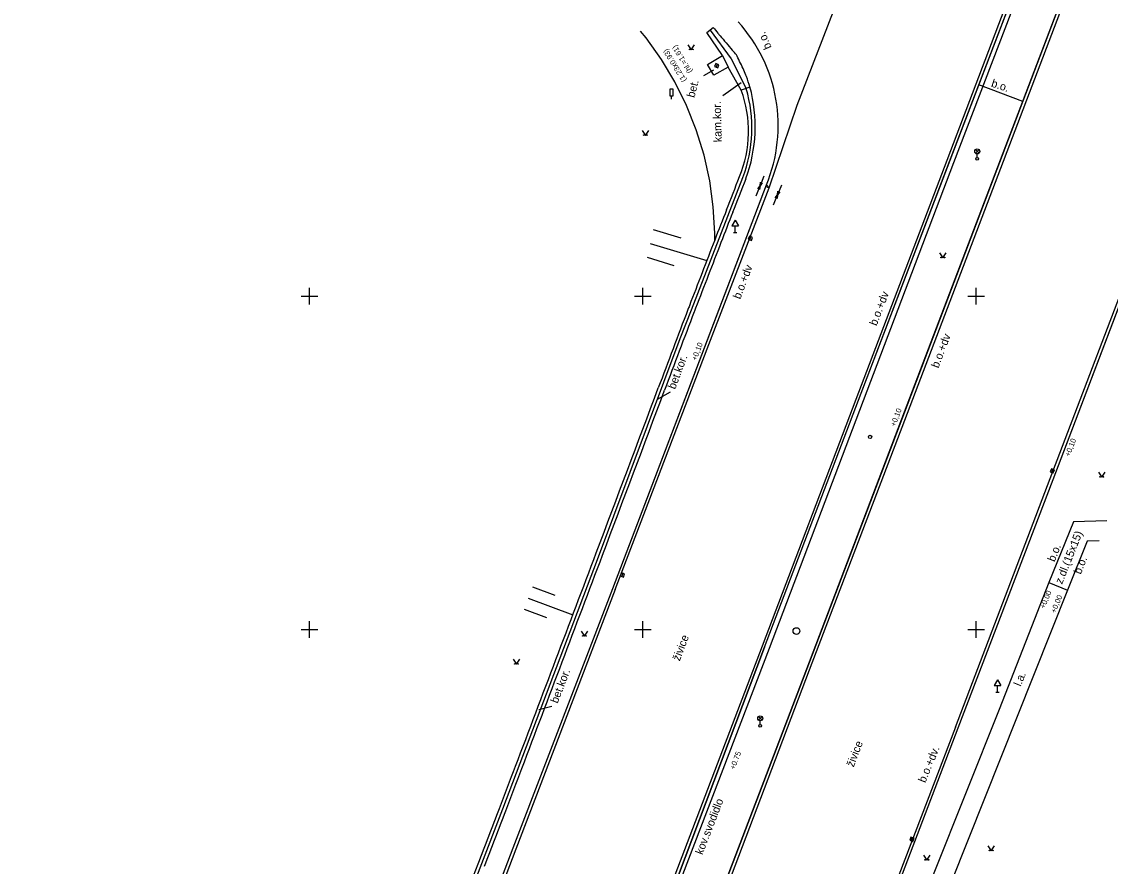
# Model space of a CAD drawing. Extents: x -599151 to -598424, y -1163476 to -1161924.
# Drawn here: x -598821.6 to -598740, y -1162867.7 to -1162804.4 of the extents above; entities that cross this region are included whole.
import ezdxf

# ---------------------------------------------------------------- set-up
doc = ezdxf.new("R2010")
doc.units = 0
for name, color, linetype in [('Vrstva 14', 7, 'Continuous'), ('Vrstva 15', 7, 'Continuous'), ('Vrstva 19', 7, 'Continuous'), ('Vrstva 21', 7, 'Continuous'), ('Vrstva 23', 7, 'Continuous'), ('Vrstva 25', 7, 'Continuous'), ('Vrstva 29', 7, 'Continuous'), ('Vrstva 41', 7, 'Continuous'), ('Vrstva 49', 7, 'Continuous'), ('Vrstva 50', 7, 'Continuous'), ('Vrstva 62', 7, 'Continuous'), ('Vrstva 63', 7, 'Continuous'), ('Vrstva 7', 7, 'Continuous')]:
    doc.layers.add(name, color=color, linetype=linetype)

msp = doc.modelspace()

# ---------------------------------------------------------------- linework, layer by layer
at = {"layer": 'Vrstva 14'}
for points in [[(-598771.62, -1162806.148), (-598771.37, -1162806.523), (-598771.12, -1162806.148)], [(-598775.059, -1162812.575), (-598774.809, -1162812.95), (-598774.559, -1162812.575)], [(-598752.759, -1162821.754), (-598752.509, -1162822.129), (-598752.259, -1162821.754)], [(-598740.845, -1162838.197), (-598740.595, -1162838.572), (-598740.345, -1162838.197)], [(-598779.637, -1162850.128), (-598779.387, -1162850.503), (-598779.137, -1162850.128)], [(-598784.733, -1162852.228), (-598784.483, -1162852.603), (-598784.233, -1162852.228)], [(-598749.14, -1162866.212), (-598748.89, -1162866.587), (-598748.64, -1162866.212)], [(-598753.956, -1162866.913), (-598753.706, -1162867.288), (-598753.456, -1162866.913)]]:
    msp.add_lwpolyline(points, dxfattribs=at)
for centre in [(-598771.495, -1162806.498), (-598771.245, -1162806.498), (-598774.934, -1162812.925), (-598774.684, -1162812.925), (-598752.634, -1162822.104), (-598752.384, -1162822.104), (-598740.72, -1162838.547), (-598740.47, -1162838.547), (-598779.512, -1162850.478), (-598779.262, -1162850.478), (-598784.608, -1162852.578), (-598784.358, -1162852.578), (-598749.015, -1162866.562), (-598748.765, -1162866.562), (-598753.831, -1162867.263), (-598753.581, -1162867.263)]:
    msp.add_circle(centre, 0.025, dxfattribs=at)
at = {"layer": 'Vrstva 15'}
msp.add_line((-598772.85, -1162810.23), (-598772.85, -1162809.98), dxfattribs=at)
msp.add_lwpolyline([(-598772.975, -1162809.98), (-598772.725, -1162809.98), (-598772.725, -1162809.48), (-598772.975, -1162809.48)], close=True, dxfattribs=at)
at = {"layer": 'Vrstva 19'}
for p, q in [((-598768.08, -1162819.307), (-598768.33, -1162819.74)), ((-598768.33, -1162819.74), (-598767.83, -1162819.74)), ((-598768.08, -1162819.307), (-598767.83, -1162819.74)), ((-598768.08, -1162820.24), (-598768.08, -1162819.74)), ((-598768.205, -1162820.24), (-598767.955, -1162820.24)), ((-598748.4, -1162853.767), (-598748.65, -1162854.2)), ((-598748.4, -1162853.767), (-598748.15, -1162854.2)), ((-598748.65, -1162854.2), (-598748.15, -1162854.2)), ((-598748.525, -1162854.7), (-598748.275, -1162854.7)), ((-598748.4, -1162854.7), (-598748.4, -1162854.2))]:
    msp.add_line(p, q, dxfattribs=at)
at = {"layer": 'Vrstva 21'}
msp.add_lwpolyline([(-598695.78, -1162664.24), (-598699.97, -1162674.3), (-598702.11, -1162679.97), (-598709.91, -1162700.89), (-598717.13, -1162720.74), (-598723.5, -1162738.84), (-598727.94, -1162752.59), (-598729.98, -1162757.92), (-598744.45, -1162796.07), (-598751.7, -1162815.01), (-598765.52, -1162851.41), (-598773.26, -1162871.58), (-598779.91, -1162889.88), (-598781.91, -1162894.82), (-598784.85, -1162901.68), (-598795.29, -1162929.3), (-598803.04, -1162949.86), (-598814.6, -1162980.19)], dxfattribs=at)
at = {"layer": 'Vrstva 23'}
msp.add_circle((-598757.97, -1162835.56), 0.125, dxfattribs=at)
at = {"layer": 'Vrstva 25'}
for p, q in [((-598769.504, -1162807.837), (-598769.416, -1162807.603)), ((-598766.984, -1162820.787), (-598766.896, -1162820.553)), ((-598744.345, -1162838.217), (-598744.255, -1162837.983)), ((-598776.574, -1162846.017), (-598776.486, -1162845.783)), ((-598754.875, -1162865.837), (-598754.785, -1162865.603))]:
    msp.add_line(p, q, dxfattribs=at)
for points in [[(-598769.388, -1162807.881), (-598769.299, -1162807.648), (-598769.532, -1162807.559), (-598769.621, -1162807.792)], [(-598766.868, -1162820.831), (-598766.779, -1162820.598), (-598767.012, -1162820.509), (-598767.101, -1162820.742)], [(-598744.228, -1162838.261), (-598744.139, -1162838.028), (-598744.372, -1162837.939), (-598744.461, -1162838.172)], [(-598776.458, -1162846.061), (-598776.369, -1162845.828), (-598776.602, -1162845.739), (-598776.691, -1162845.972)], [(-598754.758, -1162865.881), (-598754.669, -1162865.648), (-598754.902, -1162865.559), (-598754.991, -1162865.792)]]:
    msp.add_lwpolyline(points, close=True, dxfattribs=at)
msp.add_circle((-598763.49, -1162850.11), 0.25, dxfattribs=at)
at = {"layer": 'Vrstva 29'}
for p, q in [((-598750.062, -1162814.279), (-598749.798, -1162814.015)), ((-598749.794, -1162814.278), (-598750.058, -1162814.013)), ((-598749.93, -1162814.61), (-598749.93, -1162814.335)), ((-598766.332, -1162856.789), (-598766.068, -1162856.525)), ((-598766.064, -1162856.788), (-598766.328, -1162856.523)), ((-598766.2, -1162857.12), (-598766.2, -1162856.845))]:
    msp.add_line(p, q, dxfattribs=at)
for centre, radius in [((-598749.93, -1162814.147), 0.188), ((-598749.93, -1162814.71), 0.1), ((-598766.2, -1162856.657), 0.188), ((-598766.2, -1162857.22), 0.1)]:
    msp.add_circle(centre, radius, dxfattribs=at)
at = {"layer": 'Vrstva 41'}
for points in [[(-598769.965, -1162805.051), (-598768.39, -1162807.22), (-598767.25, -1162809.44)], [(-598769.615, -1162820.281), (-598769.723, -1162818.311), (-598769.99, -1162816.355), (-598770.414, -1162814.428), (-598770.993, -1162812.542), (-598771.723, -1162810.708), (-598772.599, -1162808.94), (-598773.615, -1162807.248), (-598774.765, -1162805.645), (-598775.17, -1162805.14)], [(-598802.77, -1162908.4), (-598801.13, -1162904.1), (-598799.86, -1162900.78), (-598798.47, -1162897.13), (-598792.68, -1162882.11), (-598785.5, -1162863.45), (-598778.41, -1162844.74), (-598772.2, -1162828.18), (-598771.36, -1162826.03), (-598767.51, -1162816.11)], [(-598774.232, -1162819.999), (-598772.144, -1162820.629)], [(-598769.613, -1162820.8), (-598769.615, -1162820.281)], [(-598774.45, -1162821.043), (-598770.204, -1162822.332)], [(-598774.668, -1162822.088), (-598772.673, -1162822.697)], [(-598783.283, -1162846.802), (-598781.611, -1162847.434)], [(-598783.593, -1162847.638), (-598780.255, -1162848.901)], [(-598783.902, -1162848.475), (-598782.237, -1162849.105)]]:
    msp.add_lwpolyline(points, dxfattribs=at)
msp.add_arc((-598777.359, -1162812.386), 10.53, 339.28834, 16.24708, dxfattribs=at)
at = {"layer": 'Vrstva 49'}
for p, q in [((-598767.639, -1162809.005), (-598769.011, -1162809.984)), ((-598765.92, -1162816.002), (-598766.216, -1162816.737)), ((-598766.216, -1162816.737), (-598766.184, -1162816.459)), ((-598766.05, -1162816.513), (-598766.216, -1162816.737)), ((-598766.513, -1162817.472), (-598766.216, -1162816.737)), ((-598766.384, -1162816.96), (-598766.216, -1162816.737)), ((-598766.216, -1162816.737), (-598766.25, -1162817.014)), ((-598764.61, -1162816.677), (-598764.906, -1162817.412)), ((-598764.906, -1162817.412), (-598764.874, -1162817.134)), ((-598764.74, -1162817.188), (-598764.906, -1162817.412)), ((-598765.203, -1162818.147), (-598764.906, -1162817.412)), ((-598765.074, -1162817.635), (-598764.906, -1162817.412)), ((-598764.906, -1162817.412), (-598764.94, -1162817.689)), ((-598773.893, -1162832.73), (-598772.921, -1162832.182)), ((-598782.805, -1162855.995), (-598781.834, -1162855.742))]:
    msp.add_line(p, q, dxfattribs=at)
msp.add_lwpolyline([(-598769.696, -1162808.05), (-598770.45, -1162808.472)], dxfattribs=at)
at = {"layer": 'Vrstva 62'}
for p, q in [((-598800, -1162825.625), (-598800, -1162824.375)), ((-598775, -1162825.625), (-598775, -1162824.375)), ((-598750, -1162825.625), (-598750, -1162824.375)), ((-598800.625, -1162825), (-598799.375, -1162825)), ((-598775.625, -1162825), (-598774.375, -1162825)), ((-598750.625, -1162825), (-598749.375, -1162825)), ((-598800.625, -1162850), (-598799.375, -1162850)), ((-598800, -1162850.625), (-598800, -1162849.375)), ((-598775.625, -1162850), (-598774.375, -1162850)), ((-598775, -1162850.625), (-598775, -1162849.375)), ((-598750.625, -1162850), (-598749.375, -1162850)), ((-598750, -1162850.625), (-598750, -1162849.375))]:
    msp.add_line(p, q, dxfattribs=at)
at = {"layer": 'Vrstva 63'}
for points in [[(-598859.45, -1163096.65), (-598854.32, -1163084.15), (-598824.47, -1163005.5), (-598816.67, -1162984.98), (-598803.24, -1162949.74), (-598780.23, -1162889.28), (-598773.478, -1162871.463), (-598765.88, -1162851.33), (-598758.84, -1162832.8), (-598745.6, -1162798.16), (-598737.25, -1162776.15), (-598728.25, -1162752.5), (-598723.5, -1162738.84), (-598717.13, -1162720.74), (-598709.91, -1162700.89), (-598702.11, -1162679.97), (-598696.15, -1162664.13), (-598695.39, -1162662.07), (-598693.97, -1162658.31)], [(-598715.54, -1162721.28), (-598721.7, -1162739.99), (-598727.72, -1162758.34), (-598733.31, -1162775.48), (-598734.01, -1162777.52), (-598762.71, -1162852.94), (-598770.32, -1162872.91), (-598777.27, -1162891.31), (-598784.14, -1162909.43), (-598799.74, -1162950.34), (-598813.33, -1162986.07), (-598821.23, -1163006.93), (-598828.55, -1163026.09), (-598835.89, -1163045.37), (-598843.55, -1163065.41), (-598852.18, -1163085.13), (-598858.28, -1163096.77)], [(-598765.74, -1162816.66), (-598765.54, -1162816.88), (-598763.42, -1162810.69), (-598748.41, -1162771.79), (-598748.62, -1162771.71)], [(-598771.08, -1162918.09), (-598770.2, -1162914.6), (-598765.71, -1162896.08), (-598764.99, -1162893.42), (-598764.39, -1162891.59), (-598759.11, -1162877.7), (-598751.35, -1162857.38), (-598744.24, -1162838.75), (-598722.51, -1162781.69)], [(-598802.47, -1162913.36), (-598791.67, -1162884.62), (-598784.72, -1162866.37), (-598777.26, -1162846.93), (-598765.74, -1162816.66)]]:
    msp.add_lwpolyline(points, dxfattribs=at)
at = {"layer": 'Vrstva 7'}
for p, q in [((-598769.04, -1162806.961), (-598768.61, -1162807.831)), ((-598766.97, -1162809.321), (-598767.62, -1162809.551)), ((-598744.55, -1162846.461), (-598743.16, -1162847.041)), ((-598751.56, -1162857.32), (-598759.33, -1162877.63))]:
    msp.add_line(p, q, dxfattribs=at)
for points in [[(-598696.37, -1162664.06), (-598702.36, -1162680), (-598710.16, -1162700.82), (-598717.38, -1162720.66), (-598723.7, -1162738.77), (-598728.46, -1162752.352), (-598730.54, -1162757.75), (-598737.46, -1162776.08), (-598745, -1162795.86), (-598752.22, -1162814.82), (-598759.04, -1162832.74), (-598766.06, -1162851.25)], [(-598765.88, -1162851.33), (-598758.84, -1162832.8), (-598752, -1162814.9), (-598745.6, -1162798.16), (-598744.77, -1162795.95), (-598742.6, -1162790.26), (-598740.02, -1162783.45), (-598737.25, -1162776.15), (-598730.28, -1162757.84), (-598728.25, -1162752.5), (-598723.5, -1162738.84), (-598717.13, -1162720.74), (-598709.91, -1162700.89), (-598702.11, -1162679.97), (-598699.97, -1162674.3), (-598696.15, -1162664.13)], [(-598762.5, -1162853.02), (-598755.36, -1162834.29), (-598748.57, -1162816.46), (-598741.19, -1162797.06), (-598733.81, -1162777.57), (-598727.52, -1162758.45), (-598721.48, -1162740.08), (-598715.31, -1162721.42), (-598707.94, -1162701.65), (-598699.86, -1162680.28), (-598694, -1162664.87)], [(-598762.71, -1162852.94), (-598755.58, -1162834.21), (-598748.79, -1162816.36), (-598741.41, -1162796.99), (-598734.01, -1162777.52), (-598733.31, -1162775.48), (-598727.72, -1162758.34), (-598721.7, -1162739.99), (-598715.54, -1162721.28)], [(-598751.56, -1162857.32), (-598744.45, -1162838.68), (-598737.4, -1162820.13), (-598730.22, -1162801.32), (-598722.69, -1162781.57)], [(-598751.35, -1162857.38), (-598744.24, -1162838.75), (-598737.18, -1162820.22), (-598730.01, -1162801.4), (-598722.51, -1162781.69)], [(-598767.62, -1162809.551), (-598768.61, -1162807.831), (-598769.68, -1162808.441), (-598770.16, -1162807.641), (-598769.04, -1162806.961), (-598770.2, -1162805.241), (-598769.73, -1162804.861)], [(-598746.523, -1162810.409), (-598749.8, -1162809.16)], [(-598777.26, -1162846.93), (-598770.39, -1162828.89), (-598765.74, -1162816.66)], [(-598777.07, -1162847.01), (-598770.17, -1162828.96), (-598765.54, -1162816.88)], [(-598765.788, -1162816.786), (-598765.54, -1162816.88)], [(-598740.21, -1162841.861), (-598742.71, -1162841.921), (-598744.55, -1162846.461), (-598748.292, -1162856.006), (-598755.699, -1162874.589), (-598763.068, -1162893.186), (-598766.93, -1162902.891), (-598767.349, -1162902.783)], [(-598740.78, -1162843.351), (-598741.7, -1162843.381), (-598743.16, -1162847.041), (-598746.949, -1162856.509), (-598754.347, -1162875.095), (-598761.657, -1162893.714), (-598765.58, -1162903.191), (-598767.967, -1162912.707), (-598769.5, -1162918.951), (-598770.86, -1162923.011), (-598774.187, -1162931.734), (-598777.94, -1162941.661), (-598779.72, -1162946.361), (-598781.26, -1162950.441), (-598783.18, -1162955.469), (-598785.69, -1162962.041), (-598787.332, -1162961.472)], [(-598802.47, -1162913.36), (-598799.24, -1162904.75), (-598791.67, -1162884.62), (-598784.72, -1162866.37), (-598777.26, -1162846.93)], [(-598777.07, -1162847.01), (-598784.52, -1162866.46), (-598791.45, -1162884.69), (-598799.01, -1162904.83), (-598802.29, -1162913.48)], [(-598766.06, -1162851.25), (-598773.72, -1162871.36), (-598780.45, -1162889.16), (-598787.89, -1162908.78), (-598795.65, -1162929.11), (-598803.47, -1162949.68)], [(-598765.88, -1162851.33), (-598773.478, -1162871.463), (-598780.23, -1162889.28), (-598787.69, -1162908.86), (-598795.42, -1162929.21), (-598803.24, -1162949.74)], [(-598799.74, -1162950.34), (-598792.31, -1162930.88), (-598784.14, -1162909.43), (-598777.27, -1162891.31), (-598770.32, -1162872.91), (-598762.71, -1162852.94)], [(-598799.53, -1162950.41), (-598792.11, -1162930.94), (-598783.92, -1162909.54), (-598777.05, -1162891.41), (-598770.09, -1162872.98), (-598762.5, -1162853.02)], [(-598771.08, -1162918.09), (-598770.2, -1162914.6), (-598765.71, -1162896.08), (-598764.99, -1162893.42), (-598764.39, -1162891.59), (-598759.11, -1162877.7), (-598751.35, -1162857.38)]]:
    msp.add_lwpolyline(points, dxfattribs=at)
for centre, radius, start, end in [((-598487.278, -1162568.683), 368.184, 219.90132, 219.9869), ((-598776.431, -1162812.214), 11.578, 337.42033, 42.24801), ((-598708.416, -1162754.158), 79.56, 219.98432, 220.16582), ((-598619.58, -1162679.175), 195.811, 220.16621, 220.58229), ((-598784.894, -1162820.778), 21.858, 39.34332, 40.58228), ((-598768.326, -1162807.196), 0.435, 26.09599, 39.34332), ((-598821.351, -1162833.168), 59.479, 24.96597, 26.09599), ((-598772.976, -1162810.646), 6.118, 20.1067, 24.96597), ((-598781.615, -1162813.808), 15.317, 17.03621, 20.1067), ((-598776.097, -1162812.627), 9.018, 337.75691, 19.94804), ((-598777.925, -1162812.277), 11.347, 339.88437, 15.10753), ((-599091.297, -1162690.834), 346.928, 338.40096, 338.84433), ((-599102.187, -1162686.534), 359.136, 338.40397, 338.83885), ((-598505.464, -1162922.77), 283.148, 158.40097, 158.89173), ((-598502.935, -1162923.747), 285.359, 158.40397, 158.89184), ((-574914.396, -1172029.717), 25570.99, 158.8917325, 158.9035579), ((-574698.478, -1172113.018), 25801.919, 158.8918392, 158.9035579), ((-597842.297, -1163180.774), 994.738, 159.106051, 159.467325), ((-597842.153, -1163180.83), 994.393, 159.105998, 159.467334), ((-598690.151, -1162857.113), 87.207, 158.90356, 159.10605), ((-598690.382, -1162857.025), 86.46, 158.90356, 159.106), ((-602905.939, -1161284.264), 4412.407, 339.295789, 339.467325), ((-602905.209, -1161284.54), 4412.126, 339.295794, 339.467333), ((-622703.779, -1153801.621), 25577.104, 339.2574833, 339.2957889), ((-622702.645, -1153802.051), 25576.392, 339.2574833, 339.2957944), ((-599728.962, -1162502.569), 1009.876, 339.064706, 339.257483), ((-599728.628, -1162502.696), 1010.018, 339.064703, 339.257483), ((-601116.664, -1161971.677), 2495.663, 338.962489, 339.064706), ((-601116.503, -1161971.738), 2495.991, 338.962489, 339.064703), ((-626889.267, -1152059.138), 30108.803, 338.9330139, 338.9624889)]:
    msp.add_arc(centre, radius, start, end, dxfattribs=at)

# ---------------------------------------------------------------- texts
at = {"layer": 'Vrstva 49'}
for s, height, rotation, p in [('b.o.', 0.6, 112.69738, (-598765.343, -1162806.36)), ('bet.', 0.6, 75.1639, (-598771.143, -1162810.159)), ('b.o.', 0.6, 341.65279, (-598748.928, -1162809.28)), ('kam.kor.', 0.6, 91.33382, (-598769.087, -1162813.453)), ('b.o.+dv', 0.6, 69.1965, (-598767.704, -1162825.273)), ('b.o.+dv', 0.6, 69.1965, (-598757.479, -1162827.268)), ('b.o.+dv', 0.6, 69.1965, (-598752.849, -1162830.44)), ('bet.kor.', 0.6, 69.35101, (-598772.585, -1162832.03)), ('z.dl.(15x15)', 0.6, 68.20941, (-598743.572, -1162846.64)), ('b.o.', 0.6, 68.56455, (-598744.125, -1162844.968)), ('b.o.', 0.6, 68.56455, (-598742.165, -1162845.902)), ('živice', 0.6, 69.2508, (-598772.243, -1162852.406)), ('bet.kor.', 0.6, 68.91145, (-598781.393, -1162855.578)), ('l.a.', 0.6, 67.38007, (-598746.672, -1162854.305)), ('živice', 0.6, 69.2508, (-598759.2, -1162860.357)), ('b.o.+dv.', 0.6, 67.68391, (-598753.829, -1162861.535)), ('kov.svodidlo', 0.59997, 68.93102, (-598770.535, -1162866.927))]:
    msp.add_text(s, height=height, rotation=rotation, dxfattribs=at).set_placement(p)
at = {"layer": 'Vrstva 50'}
for s, rotation, p in [('(1.23x0.93)', 121.53494, (-598771.709, -1162808.801)), ('(hl.=1.61)', 121.53494, (-598771.274, -1162808.139)), ('+0,10', 69.1965, (-598770.993, -1162829.872)), ('+0,10', 69.1965, (-598756.081, -1162834.809)), ('+0,10', 69.1965, (-598743.001, -1162837.07)), ('+0,00', 67.51291, (-598744.883, -1162848.469)), ('+0,00', 67.51291, (-598744.068, -1162848.8)), ('+0.75', 69.11223, (-598768.122, -1162860.539))]:
    msp.add_text(s, height=0.4, rotation=rotation, dxfattribs=at).set_placement(p)

doc.saveas('drawing.dxf')
